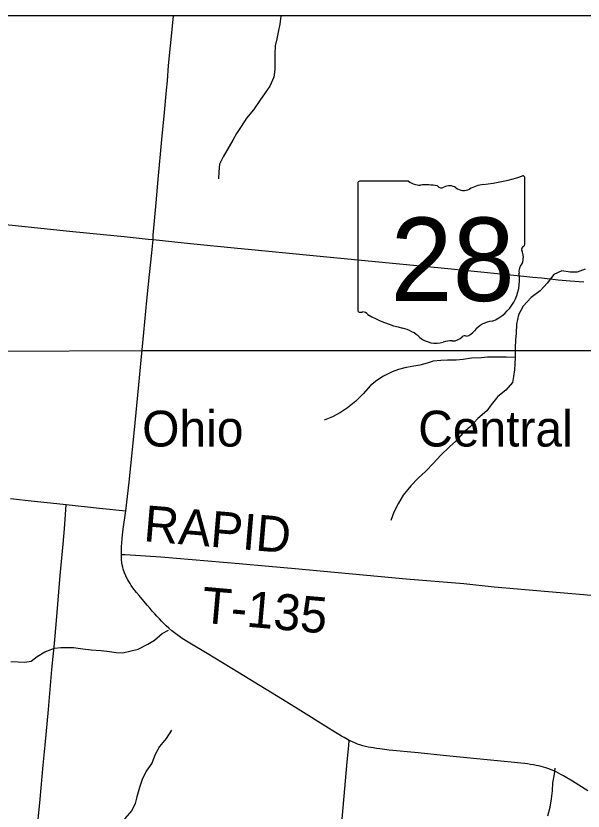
# Model space of a CAD drawing. Extents: x 0 to 1052, y -194 to 246.
# Drawn here: x 2.91 to 3.805, y 19.749 to 21.005 of the extents above; entities that cross this region are included whole.
import ezdxf

# ---------------------------------------------------------------- set-up
doc = ezdxf.new("R2010")
doc.units = 0
for name, color, linetype in [('GM_X_Corporation', 7, 'Continuous'), ('GM_X_County_Road', 7, 'Continuous'), ('GM_X_Minor_River', 7, 'Continuous'), ('GM_X_Rail_Line', 7, 'Continuous'), ('GM_X_Rail_Line_Text', 7, 'Continuous'), ('GM_X_State_Location', 7, 'Continuous'), ('GM_X_State_Route', 7, 'Continuous'), ('GM_X_State_Shield', 7, 'Continuous'), ('GM_X_Township_Road', 7, 'Continuous'), ('GM_X_Township_Road_Text', 7, 'Continuous')]:
    doc.layers.add(name, color=color, linetype=linetype)

msp = doc.modelspace()

# ---------------------------------------------------------------- linework, layer by layer
at = {"layer": 'GM_X_Corporation'}
for points in [[(5.1788, 17.6981), (5.491, 17.9457), (6.1888, 18.4644), (6.5994, 18.7694), (6.8785, 18.9763), (8.1871, 19.9814), (8.6571, 20.341), (8.7822, 20.435), (8.7822, 21.0055), (1.9822, 21.0055), (1.9822, 14.2055)], [(5.1788, 17.6981), (5.491, 17.9457), (6.1888, 18.4644), (6.152, 18.6129), (5.992, 19.3448), (5.9283, 19.6076), (5.6935, 20.5776), (5.5898, 21.0055), (1.9822, 21.0055), (1.9822, 14.2055)]]:
    msp.add_lwpolyline(points, dxfattribs=at)
at = {"layer": 'GM_X_County_Road'}
for points in [[(2.9008, 20.2433), (2.9384, 20.239), (2.9643, 20.2363), (2.9891, 20.2336)], [(2.9433, 19.7201), (2.948, 19.7683), (2.9528, 19.8221), (2.9558, 19.8537), (2.9608, 19.91), (2.9664, 19.9731), (2.9703, 20.0139), (2.9738, 20.0504), (2.9796, 20.1215), (2.9843, 20.171), (2.9862, 20.1952), (2.9879, 20.2181), (2.9891, 20.2336)], [(2.9891, 20.2336), (3.0415, 20.2279), (3.0829, 20.2235)], [(3.4225, 19.7127), (3.4324, 19.8272), (3.435, 19.8532), (3.4358, 19.8611)]]:
    msp.add_lwpolyline(points, dxfattribs=at)
at = {"layer": 'GM_X_Minor_River'}
for points in [[(3.3278, 21.0055), (3.3277, 21.0048), (3.3264, 20.9923), (3.3236, 20.9798), (3.3215, 20.9692), (3.3191, 20.9582), (3.3182, 20.9453), (3.3184, 20.9351), (3.3186, 20.921), (3.3169, 20.9089), (3.3107, 20.8946), (3.3033, 20.8837), (3.2948, 20.8716), (3.2847, 20.8573), (3.2735, 20.8438), (3.2654, 20.8306), (3.2576, 20.8197), (3.2522, 20.8092), (3.2463, 20.799), (3.2366, 20.7828), (3.2311, 20.7711), (3.2298, 20.7593), (3.2293, 20.748)], [(3.8085, 20.6053), (3.7956, 20.6005), (3.7849, 20.6007), (3.7717, 20.6027), (3.7587, 20.5972), (3.7482, 20.5833), (3.7374, 20.5709), (3.7232, 20.5605), (3.7105, 20.547), (3.7031, 20.5334), (3.6999, 20.5186), (3.6993, 20.5042), (3.6984, 20.4932), (3.6979, 20.4815), (3.6981, 20.4659), (3.6976, 20.456), (3.6967, 20.4466), (3.695, 20.4356), (3.6937, 20.4261), (3.6829, 20.4141), (3.6707, 20.4044), (3.6598, 20.3912), (3.6529, 20.3815), (3.6391, 20.3695), (3.6271, 20.3571), (3.616, 20.3466), (3.6044, 20.3339), (3.594, 20.3249), (3.5798, 20.311), (3.569, 20.299), (3.5567, 20.2863), (3.5447, 20.2754), (3.5332, 20.263), (3.5212, 20.2484), (3.5135, 20.2356), (3.5064, 20.2213)], [(3.6981, 20.4659), (3.6836, 20.4665), (3.6673, 20.4663), (3.654, 20.4665), (3.6445, 20.4655), (3.6289, 20.4649), (3.6156, 20.4628), (3.6046, 20.4618), (3.5909, 20.4616), (3.5806, 20.461), (3.5685, 20.46), (3.5589, 20.4567), (3.5471, 20.4538), (3.5346, 20.4517), (3.5239, 20.4496), (3.5136, 20.4467), (3.5037, 20.4434), (3.4899, 20.4363), (3.4792, 20.4293), (3.4696, 20.4214), (3.458, 20.4083), (3.4461, 20.3967), (3.433, 20.3866), (3.4219, 20.3788), (3.4093, 20.3721), (3.3963, 20.3666)], [(3.5064, 20.2213), (3.5013, 20.2084)], [(2.9017, 19.9854), (2.913, 19.9849), (2.9237, 19.9847), (2.9336, 19.9861), (2.9432, 19.9936), (2.955, 20.001), (2.9703, 20.0065), (2.9802, 20.0075), (2.9908, 20.0078), (3.0007, 20.0076), (3.0151, 20.0059), (3.0284, 20.0042), (3.0439, 20.0029), (3.0572, 20.0012), (3.0678, 19.9996), (3.0785, 19.9994), (3.0914, 20.0023), (3.1025, 20.0052), (3.1178, 20.013), (3.1281, 20.0193), (3.1404, 20.0297), (3.1503, 20.0353)], [(3.1551, 19.8769), (3.1466, 19.8642), (3.1365, 19.8514), (3.1295, 19.8386), (3.124, 19.825), (3.1151, 19.8122), (3.1089, 19.7993), (3.1049, 19.7865), (3.1005, 19.7717), (3.0977, 19.7611), (3.0923, 19.7502), (3.0815, 19.7374), (3.0763, 19.725), (3.0743, 19.7102), (3.073, 19.7003), (3.0717, 19.6905), (3.0666, 19.6761), (3.0611, 19.6614), (3.0567, 19.6497), (3.0501, 19.6369), (3.0371, 19.6275), (3.0233, 19.6205), (3.0163, 19.6073), (3.0139, 19.5952)], [(3.7496, 19.7421), (3.7532, 19.7557), (3.7553, 19.7689), (3.757, 19.7815), (3.7575, 19.794), (3.76, 19.8076), (3.7613, 19.8171)]]:
    msp.add_lwpolyline(points, dxfattribs=at)
at = {"layer": 'GM_X_Rail_Line'}
msp.add_lwpolyline([(1.9822, 20.4716), (2.0551, 20.4708), (2.4106, 20.4737), (3.1102, 20.4767), (3.8818, 20.4767), (4.2729, 20.4769), (4.6986, 20.4854), (5.3445, 20.496), (5.674, 20.5018), (6.3876, 20.5117), (6.862, 20.5208), (7.7527, 20.5376), (8.5619, 20.5538), (8.7822, 20.5583)], dxfattribs=at)
at = {"layer": 'GM_X_State_Route'}
for points in [[(3.8127, 19.7811), (3.7886, 19.7964), (3.7742, 19.8051), (3.7702, 19.8072), (3.7661, 19.8095), (3.7626, 19.8111), (3.7588, 19.8129), (3.7548, 19.8145), (3.7508, 19.8161), (3.7463, 19.8175), (3.7426, 19.8187), (3.7389, 19.8197), (3.7348, 19.8208), (3.7313, 19.8215), (3.727, 19.8224), (3.7223, 19.8231), (3.7172, 19.8239), (3.7129, 19.8244), (3.7068, 19.8251), (3.7018, 19.8257), (3.6966, 19.8262), (3.6319, 19.8325), (3.5843, 19.8372), (3.5448, 19.8413), (3.499, 19.8458), (3.4842, 19.8475), (3.4788, 19.8483), (3.4737, 19.849), (3.4699, 19.8497), (3.4657, 19.8505), (3.4615, 19.8515), (3.4572, 19.8526), (3.4525, 19.8541), (3.4489, 19.8553), (3.4449, 19.857), (3.4408, 19.8587), (3.4372, 19.8605), (3.4358, 19.8611), (3.4329, 19.8626), (3.4278, 19.8654), (3.4236, 19.8677), (3.4197, 19.8701), (3.4141, 19.8735), (3.4098, 19.8761), (3.4032, 19.8802), (3.355, 19.9104), (3.3307, 19.9254), (3.3047, 19.9413), (3.2602, 19.9686), (3.2114, 19.9983), (3.1816, 20.0163), (3.1721, 20.0222), (3.1676, 20.0253), (3.1639, 20.0278), (3.1598, 20.031), (3.1555, 20.0343), (3.1512, 20.0381), (3.1466, 20.0422), (3.1435, 20.0453), (3.1395, 20.0492), (3.136, 20.0529), (3.1318, 20.0574), (3.1289, 20.0607), (3.1249, 20.0653), (3.1216, 20.0691), (3.1172, 20.0742), (3.1143, 20.0776), (3.1119, 20.0804), (3.1088, 20.0842), (3.1039, 20.09), (3.1, 20.0948), (3.0943, 20.1022), (3.0917, 20.1059), (3.0897, 20.1089), (3.0877, 20.1121), (3.0861, 20.1148), (3.0844, 20.1181), (3.083, 20.121), (3.081, 20.1256), (3.079, 20.1316), (3.0782, 20.1348), (3.0774, 20.1383), (3.0767, 20.142), (3.0764, 20.1462), (3.0761, 20.1495), (3.0761, 20.154), (3.076, 20.1549), (3.076, 20.1577), (3.0763, 20.1629), (3.0765, 20.1676), (3.0768, 20.1718), (3.0775, 20.1807), (3.0789, 20.1949), (3.0829, 20.2235), (3.0882, 20.2688), (3.0961, 20.3461), (3.1038, 20.4227), (3.1074, 20.4617), (3.1117, 20.5056), (3.1165, 20.5557), (3.1207, 20.5971), (3.1242, 20.6311), (3.126, 20.6523), (3.1265, 20.659), (3.131, 20.7103), (3.1337, 20.7413), (3.1405, 20.8162), (3.1435, 20.8471), (3.1473, 20.8879), (3.1487, 20.9028), (3.1507, 20.9269), (3.1568, 20.9894), (3.1583, 21.0055)], [(2.7052, 20.6953), (2.7575, 20.69), (2.7958, 20.6858), (2.8465, 20.6806), (2.9188, 20.6733), (2.9942, 20.6654), (3.0479, 20.66), (3.0807, 20.6568), (3.1184, 20.653), (3.126, 20.6523), (3.1605, 20.6487), (3.1852, 20.6461), (3.2594, 20.6386), (3.2873, 20.636), (3.3627, 20.6283), (3.4604, 20.6191), (3.581, 20.6074), (3.6855, 20.5969), (3.7114, 20.5943), (3.7257, 20.5929), (3.7399, 20.5916), (3.7658, 20.5887), (3.785, 20.5872), (3.8061, 20.5854)]]:
    msp.add_lwpolyline(points, dxfattribs=at)
at = {"layer": 'GM_X_State_Shield'}
for p, q in [((3.4494, 20.7411), (3.4494, 20.541)), ((3.5292, 20.7445), (3.452, 20.7445)), ((3.713, 20.6448), (3.713, 20.7495)), ((3.713, 20.6448), (3.713, 20.6448))]:
    msp.add_line(p, q, dxfattribs=at)
for centre, radius, start, end in [((3.6191, 21.0173), 0.2796, 275.8445, 288.9065), ((3.7101, 20.7499), 0.00294, 351.8621, 97.738), ((3.4524, 20.7415), 0.00305, 98.1301, 188.1301), ((3.5476, 20.7677), 0.0296, 231.6195, 271.1119), ((3.6548, 20.6834), 0.0563, 97.3462, 120.7689), ((3.5574, 20.6322), 0.1064, 80.4867, 94.9883), ((3.5816, 20.7425), 0.00855, 219.7921, 297.1024), ((3.5941, 20.7194), 0.0178, 54.4667, 119.1411), ((3.617, 20.7511), 0.0214, 233.8562, 294.8282), ((3.7124, 20.6371), 0.00454, 107.944, 210.337), ((3.7099, 20.6444), 0.00314, 289.6038, 7.7341), ((3.6835, 20.6239), 0.0273, 340.033, 23.6496), ((3.7236, 20.601), 0.0198, 136.8065, 186.9296), ((3.6348, 20.5877), 0.0699, 292.3089, 8.9858), ((3.4524, 20.5405), 0.00308, 171.9584, 258.3066), ((3.4529, 20.561), 0.0235, 267.339, 280.6039), ((3.4577, 20.5294), 0.00848, 29.7484, 93.2717), ((3.5648, 20.7092), 0.2019, 240.4129, 257.1985), ((3.6643, 20.4848), 0.0383, 94.4031, 142.5768), ((3.5046, 20.451), 0.0632, 47.1842, 75.836), ((3.6157, 20.5216), 0.0226, 282.8732, 323.2771), ((3.5729, 20.5284), 0.0401, 230.7004, 286.2918), ((3.5961, 20.4592), 0.0329, 85.6951, 111.2099), ((3.599, 20.5134), 0.0214, 268.777, 315.5493), ((3.6183, 20.494), 0.00601, 65.7517, 132.6484)]:
    msp.add_arc(centre, radius, start, end, dxfattribs=at)
at = {"layer": 'GM_X_Township_Road'}
msp.add_lwpolyline([(3.076, 20.1549), (3.0822, 20.1545), (3.1382, 20.1508), (3.262, 20.1402), (3.3091, 20.1362), (3.3505, 20.1325), (3.5257, 20.1164), (3.6167, 20.1087), (3.6649, 20.1038), (3.8365, 20.0888), (3.9336, 20.0809), (3.9739, 20.0774), (4.0191, 20.0735), (4.1045, 20.0657), (4.2269, 20.0551), (4.3385, 20.0444), (4.3401, 20.0443)], dxfattribs=at)

# ---------------------------------------------------------------- texts
at = {"layer": 'GM_X_Rail_Line_Text'}
for s, p in [('Ohio', (3.1089, 20.3252)), ('Central', (3.5447, 20.3252))]:
    msp.add_text(s, height=0.05663, rotation=0, dxfattribs=at).set_placement(p)
at = {"layer": 'GM_X_State_Location'}
for s in ['s', 'r']:
    msp.add_text(s, height=0.000189, dxfattribs=at).set_placement((3.5782, 20.6277))
msp.add_text('28', height=0.000189, rotation=0, dxfattribs=at).set_placement((3.5306, 20.6139))
at = {"layer": 'GM_X_State_Shield'}
msp.add_text('28', height=0.13184, dxfattribs=at).set_placement((3.5011, 20.5551))
at = {"layer": 'GM_X_Township_Road_Text'}
for s, rotation, p in [('RAPID', 355.2171, (3.11, 20.1759)), ('T-135', 354.957, (3.201, 20.0471))]:
    msp.add_text(s, height=0.05682, rotation=rotation, dxfattribs=at).set_placement(p)

doc.saveas('drawing.dxf')
